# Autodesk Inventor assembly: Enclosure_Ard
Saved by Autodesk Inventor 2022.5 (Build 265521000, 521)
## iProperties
Created: 2024-05
Part Number: Enclosure_Ard
Document SubType Name: Assembly
Designer: AdminForWorker
Title: Enclosure_Ard v7
Author: AdminForWorker
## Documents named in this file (3)
- c:\worker\convert-fusion-r02-cosv3\tmp\job-1\690\temp\files\8c865ac9-6b04-483d-a915-0dc5ec768b47\19251042-dcec-4f8b-ad01-cdc034f44ba6.iam
- c:\worker\convert-fusion-r02-cosv3\tmp\job-1\690\temp\files\8c865ac9-6b04-483d-a915-0dc5ec768b47\uno_case_base v1.ipt
- c:\worker\convert-fusion-r02-cosv3\tmp\job-1\690\temp\files\8c865ac9-6b04-483d-a915-0dc5ec768b47\uno_case_lid v3.ipt
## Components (2 placed, 2 different names)
1. uno_case_base v1:1
2. uno_case_lid v3:1
